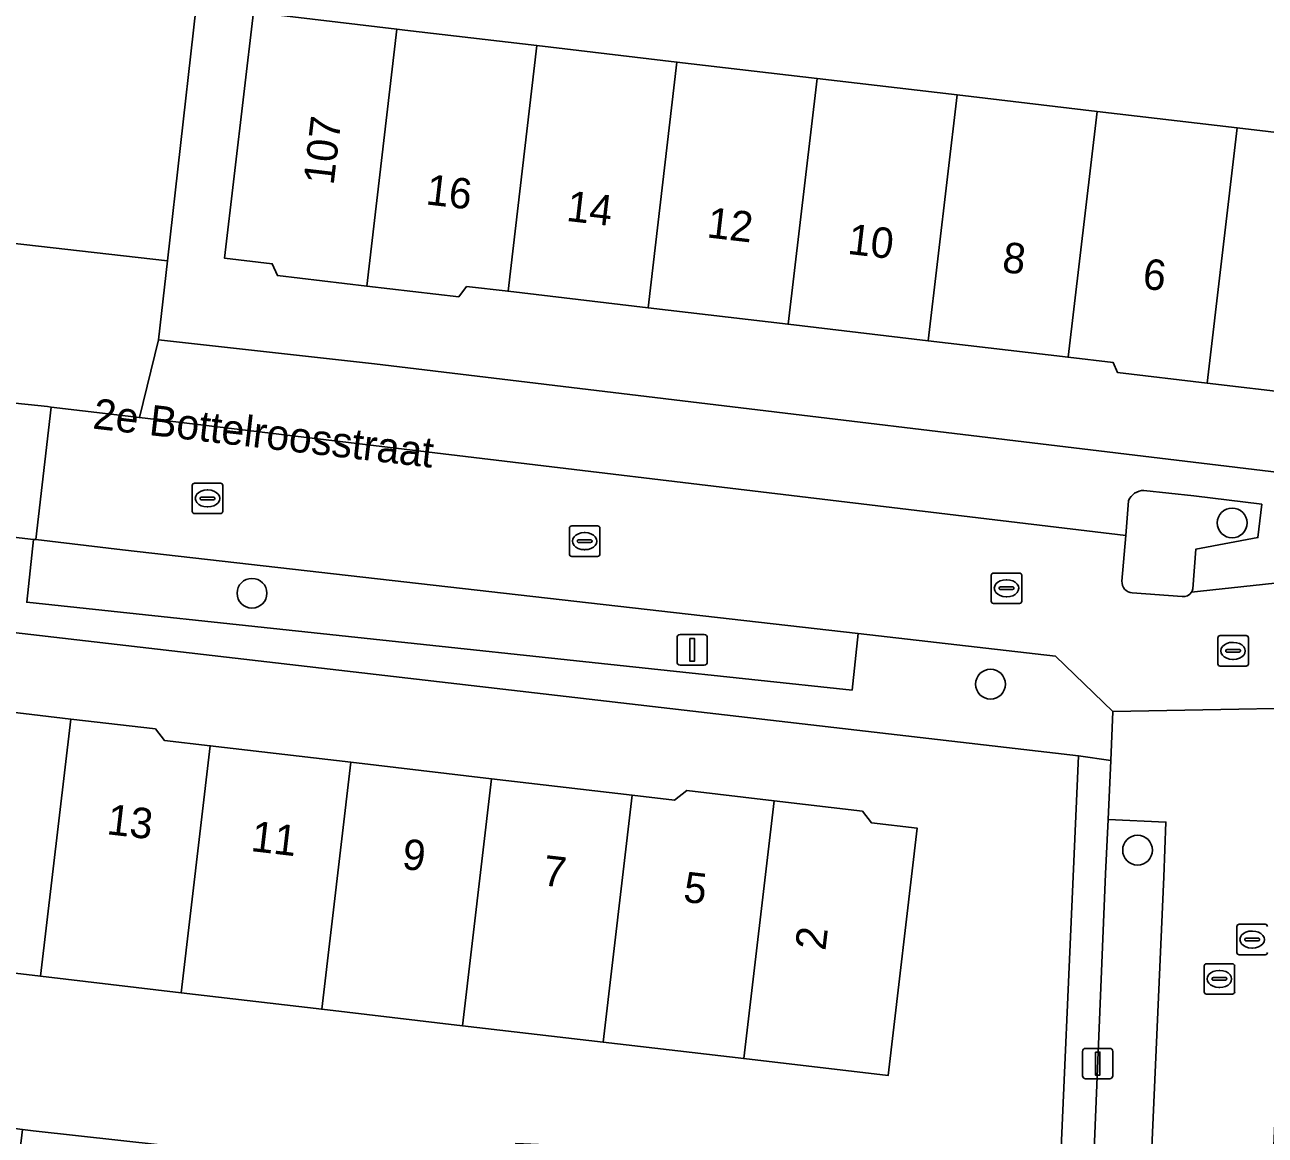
# Model space of a CAD drawing. Extents: x 162250 to 162661, y 380743 to 381606.
# Drawn here: x 162306.99 to 162347.69, y 381101.54 to 381138 of the extents above; entities that cross this region are included whole.
import ezdxf

# ---------------------------------------------------------------- set-up
doc = ezdxf.new("R2010")
doc.units = 0
for name, color, linetype in [('IMGEO_Boom', 7, 'Continuous'), ('IMGEO_Erf', 7, 'Continuous'), ('IMGEO_Groenvoorziening', 7, 'Continuous'), ('IMGEO_Kolk', 7, 'Continuous'), ('IMGEO_Lichtmast', 7, 'Continuous'), ('IMGEO_Openbare_ruimte_label', 7, 'Continuous'), ('IMGEO_Pand', 7, 'Continuous'), ('IMGEO_Pand_nummerreeks', 7, 'Continuous'), ('IMGEO_Parkeervlak_open', 7, 'Continuous'), ('IMGEO_Rijbaan_lokaal_gesloten', 7, 'Continuous'), ('IMGEO_Rijbaan_lokaal_open', 7, 'Continuous'), ('IMGEO_Rioolput', 7, 'Continuous'), ('IMGEO_Voetpad_open', 7, 'Continuous'), ('IMGEO_Woonerf_open', 7, 'Continuous')]:
    doc.layers.add(name, color=color, linetype=linetype)

msp = doc.modelspace()

# ---------------------------------------------------------------- linework, layer by layer
at = {"layer": 'IMGEO_Boom'}
for centre in [(162346.603, 381121.642), (162314.442, 381119.334), (162338.675, 381116.35), (162343.5, 381110.9)]:
    msp.add_circle(centre, 0.489, dxfattribs=at)
at = {"layer": 'IMGEO_Erf'}
for points in [[(162313.381, 381145.4), (162311.664, 381130.249), (162311.37, 381127.65), (162318.458, 381126.867), (162352.33, 381122.793), (162369.33, 381123.227), (162367.515, 381181.772)], [(162348.77, 381125.881), (162345.78, 381126.233), (162342.845, 381126.578), (162342.702, 381126.91), (162341.221, 381127.084), (162336.627, 381127.625), (162332.033, 381128.165), (162327.438, 381128.706), (162322.844, 381129.247), (162321.481, 381129.407), (162321.225, 381129.063), (162318.206, 381129.419), (162315.274, 381129.764), (162315.107, 381130.151), (162313.537, 381130.336), (162314.487, 381138.409), (162319.199, 381137.855), (162319.453, 381137.825), (162323.793, 381137.314), (162328.387, 381136.774), (162332.981, 381136.233), (162337.576, 381135.693), (162342.17, 381135.152), (162346.765, 381134.612), (162351.48, 381134.057)]]:
    msp.add_lwpolyline(points, dxfattribs=at)
for points in [[(162341.565, 381113.994), (162300.19, 381118.786), (162298.069, 381100.412), (162302.196, 381099.936), (162302.502, 381102.301), (162306.912, 381101.731), (162307.261, 381101.686), (162311.531, 381101.218), (162316.15, 381100.712), (162320.788, 381100.203), (162320.754, 381099.942), (162320.583, 381098.618), (162322.993, 381098.336), (162323.098, 381101.264), (162325.575, 381101.155), (162325.478, 381098.962), (162329.957, 381098.765), (162334.625, 381098.559), (162334.521, 381096.197), (162340.767, 381095.921)], [(162312.118, 381106.22), (162307.503, 381106.762), (162302.77, 381107.317), (162303.72, 381115.418), (162305.233, 381115.24), (162305.471, 381115.559), (162308.494, 381115.204), (162311.273, 381114.878), (162311.568, 381114.505), (162313.07, 381114.329), (162317.684, 381113.787), (162322.299, 381113.246), (162326.914, 381112.705), (162328.309, 381112.541), (162328.707, 381112.855), (162331.571, 381112.519), (162334.469, 381112.179), (162334.767, 381111.802), (162336.266, 381111.626), (162335.313, 381103.499), (162330.578, 381104.055), (162325.963, 381104.596), (162321.348, 381105.137), (162316.733, 381105.679)]]:
    msp.add_lwpolyline(points, close=True, dxfattribs=at)
at = {"layer": 'IMGEO_Groenvoorziening'}
for points in [[(162347.572, 381122.257), (162345.341, 381122.532), (162343.709, 381122.71)], [(162343.202, 381122.372), (162343.109, 381121.225), (162342.988, 381119.733)], [(162345.314, 381119.477), (162345.409, 381120.777), (162347.447, 381121.16), (162347.572, 381122.257)], [(162343.326, 381119.352), (162344.965, 381119.224)]]:
    msp.add_lwpolyline(points, dxfattribs=at)
for centre, radius, start, end in [((162343.704, 381122.168), 0.542, 89.4614, 157.9187), ((162343.34, 381119.705), 0.353, 175.4324, 267.7226), ((162345.004, 381119.537), 0.315, 262.9099, 327.1652), ((162345.019, 381119.532), 0.3, 326.4206, 349.4436)]:
    msp.add_arc(centre, radius, start, end, dxfattribs=at)
at = {"layer": 'IMGEO_Kolk'}
for p, q in [((162312.482, 381122.022), (162312.482, 381122.874)), ((162312.557, 381122.948), (162313.409, 381122.948)), ((162313.483, 381122.874), (162313.483, 381122.022)), ((162312.741, 381122.442), (162312.741, 381122.454)), ((162313.179, 381122.405), (162312.781, 381122.405)), ((162312.784, 381122.491), (162313.182, 381122.491)), ((162312.97, 381122.728), (162312.995, 381122.728)), ((162313.225, 381122.454), (162313.225, 381122.442)), ((162312.993, 381122.168), (162312.968, 381122.168)), ((162313.409, 381121.948), (162312.557, 381121.948)), ((162324.857, 381120.619), (162324.857, 381121.471)), ((162324.932, 381121.545), (162325.784, 381121.545)), ((162325.345, 381121.325), (162325.37, 381121.325)), ((162325.858, 381121.471), (162325.858, 381120.619)), ((162325.116, 381121.039), (162325.116, 381121.051)), ((162325.554, 381121.002), (162325.156, 381121.002)), ((162325.159, 381121.088), (162325.557, 381121.088)), ((162325.368, 381120.765), (162325.343, 381120.765)), ((162325.6, 381121.051), (162325.6, 381121.039)), ((162325.784, 381120.545), (162324.932, 381120.545)), ((162338.773, 381119.998), (162339.625, 381119.998)), ((162338.698, 381119.072), (162338.698, 381119.924)), ((162339, 381119.541), (162339.398, 381119.541)), ((162339.186, 381119.778), (162339.211, 381119.778)), ((162339.699, 381119.924), (162339.699, 381119.072)), ((162338.957, 381119.492), (162338.957, 381119.504)), ((162339.395, 381119.455), (162338.997, 381119.455)), ((162339.209, 381119.218), (162339.184, 381119.218)), ((162339.441, 381119.504), (162339.441, 381119.492)), ((162339.625, 381118.998), (162338.773, 381118.998)), ((162345.684, 381106.246), (162345.684, 381107.098)), ((162345.759, 381107.172), (162346.611, 381107.172)), ((162346.172, 381106.952), (162346.197, 381106.952)), ((162346.685, 381107.098), (162346.685, 381106.246)), ((162345.943, 381106.666), (162345.943, 381106.678)), ((162346.381, 381106.629), (162345.983, 381106.629)), ((162345.986, 381106.715), (162346.384, 381106.715)), ((162346.427, 381106.678), (162346.427, 381106.666)), ((162346.611, 381106.172), (162345.759, 381106.172)), ((162346.195, 381106.392), (162346.17, 381106.392))]:
    msp.add_line(p, q, dxfattribs=at)
for points in [[(162312.482, 381122.022), (162312.482, 381122.874)], [(162312.557, 381122.948), (162313.409, 381122.948)], [(162313.483, 381122.874), (162313.483, 381122.022)], [(162313.409, 381121.948), (162312.557, 381121.948)], [(162324.857, 381120.619), (162324.857, 381121.471)], [(162324.932, 381121.545), (162325.784, 381121.545)], [(162325.858, 381121.471), (162325.858, 381120.619)], [(162325.784, 381120.545), (162324.932, 381120.545)], [(162338.773, 381119.998), (162339.625, 381119.998)], [(162338.698, 381119.072), (162338.698, 381119.924)], [(162339.699, 381119.924), (162339.699, 381119.072)], [(162339.625, 381118.998), (162338.773, 381118.998)], [(162345.684, 381106.246), (162345.684, 381107.098)], [(162345.759, 381107.172), (162346.611, 381107.172)], [(162346.685, 381107.098), (162346.685, 381106.246)], [(162346.611, 381106.172), (162345.759, 381106.172)]]:
    msp.add_lwpolyline(points, dxfattribs=at)
for centre, radius, start, end in [((162312.559, 381122.872), 0.0765, 91.552, 178.448), ((162312.559, 381122.872), 0.0765, 91.552, 178.448), ((162313.407, 381122.872), 0.0765, 1.552, 88.448), ((162313.407, 381122.872), 0.0765, 1.552, 88.448), ((162312.781, 381122.451), 0.0403, 85.8775, 175.7526), ((162312.778, 381122.441), 0.0366, 178.938, 274.7102), ((162313.182, 381122.448), 0.043, 264.8664, 352.4533), ((162313.186, 381122.453), 0.0386, 1.7309, 96.639), ((162312.559, 381122.024), 0.0765, 181.552, 268.448), ((162312.559, 381122.024), 0.0765, 181.552, 268.448), ((162313.407, 381122.024), 0.0765, 271.552, 358.448), ((162313.407, 381122.024), 0.0765, 271.552, 358.448), ((162324.934, 381121.469), 0.0765, 91.552, 178.448), ((162324.934, 381121.469), 0.0765, 91.552, 178.448), ((162325.782, 381121.469), 0.0765, 1.552, 88.448), ((162325.782, 381121.469), 0.0765, 1.552, 88.448), ((162325.156, 381121.048), 0.0403, 85.8775, 175.7526), ((162325.153, 381121.038), 0.0366, 178.938, 274.7102), ((162325.557, 381121.045), 0.043, 264.8664, 352.4533), ((162325.561, 381121.05), 0.0386, 1.7309, 96.639), ((162324.934, 381120.621), 0.0765, 181.552, 268.448), ((162324.934, 381120.621), 0.0765, 181.552, 268.448), ((162325.782, 381120.621), 0.0765, 271.552, 358.448), ((162325.782, 381120.621), 0.0765, 271.552, 358.448), ((162338.775, 381119.922), 0.0765, 91.552, 178.448), ((162338.775, 381119.922), 0.0765, 91.552, 178.448), ((162339.623, 381119.922), 0.0765, 1.552, 88.448), ((162339.623, 381119.922), 0.0765, 1.552, 88.448), ((162338.997, 381119.501), 0.0403, 85.8775, 175.7526), ((162339.402, 381119.503), 0.0386, 1.7309, 96.639), ((162338.994, 381119.491), 0.0366, 178.938, 274.7102), ((162339.398, 381119.498), 0.043, 264.8664, 352.4533), ((162338.775, 381119.074), 0.0765, 181.552, 268.448), ((162338.775, 381119.074), 0.0765, 181.552, 268.448), ((162339.623, 381119.074), 0.0765, 271.552, 358.448), ((162339.623, 381119.074), 0.0765, 271.552, 358.448), ((162345.761, 381107.096), 0.0765, 91.552, 178.448), ((162345.761, 381107.096), 0.0765, 91.552, 178.448), ((162346.609, 381107.096), 0.0765, 1.552, 88.448), ((162346.609, 381107.096), 0.0765, 1.552, 88.448), ((162345.983, 381106.675), 0.0403, 85.8775, 175.7526), ((162345.98, 381106.665), 0.0366, 178.938, 274.7102), ((162346.384, 381106.672), 0.043, 264.8664, 352.4533), ((162346.388, 381106.677), 0.0386, 1.7309, 96.639), ((162345.761, 381106.248), 0.0765, 181.552, 268.448), ((162345.761, 381106.248), 0.0765, 181.552, 268.448), ((162346.609, 381106.248), 0.0765, 271.552, 358.448), ((162346.609, 381106.248), 0.0765, 271.552, 358.448)]:
    msp.add_arc(centre, radius, start, end, dxfattribs=at)
for centre, major_axis, ratio, start_param, end_param in [((162312.969, 381122.448), (-0.387, 0.002), 0.722429, 4.712389, 7.853982), ((162312.994, 381122.448), (-0.39, 0.002), 0.717154, 1.570796, 4.712389), ((162325.344, 381121.045), (-0.387, 0.002), 0.722429, 4.712389, 7.853982), ((162325.369, 381121.045), (-0.39, 0.002), 0.717154, 1.570796, 4.712389), ((162339.185, 381119.498), (-0.387, 0.002), 0.722429, 4.712389, 7.853982), ((162339.21, 381119.498), (-0.39, 0.002), 0.717154, 1.570796, 4.712389), ((162346.171, 381106.672), (-0.387, 0.002), 0.722429, 4.712389, 7.853982), ((162346.196, 381106.672), (-0.39, 0.002), 0.717154, 1.570796, 4.712389)]:
    msp.add_ellipse(centre, major_axis=major_axis, ratio=ratio, start_param=start_param, end_param=end_param, dxfattribs=at)
at = {"layer": 'IMGEO_Lichtmast'}
for p, q in [((162328.49, 381117.978), (162329.28, 381117.978)), ((162329.28, 381117.978), (162328.49, 381117.978)), ((162328.39, 381117.078), (162328.39, 381117.878)), ((162328.39, 381117.878), (162328.39, 381117.078)), ((162329.38, 381117.878), (162329.38, 381117.078)), ((162329.38, 381117.078), (162329.38, 381117.878)), ((162329.28, 381116.978), (162328.49, 381116.978)), ((162328.49, 381116.978), (162329.28, 381116.978)), ((162341.696, 381103.493), (162341.696, 381104.293)), ((162341.696, 381104.293), (162341.696, 381103.493)), ((162341.796, 381104.393), (162342.586, 381104.393)), ((162342.586, 381104.393), (162341.796, 381104.393)), ((162342.686, 381104.293), (162342.686, 381103.493)), ((162342.686, 381103.493), (162342.686, 381104.293)), ((162342.586, 381103.393), (162341.796, 381103.393)), ((162341.796, 381103.393), (162342.586, 381103.393))]:
    msp.add_line(p, q, dxfattribs=at)
for points in [[(162328.81, 381117.853), (162328.96, 381117.853), (162328.96, 381117.103), (162328.81, 381117.103), (162328.81, 381117.853)], [(162342.116, 381104.268), (162342.266, 381104.268), (162342.266, 381103.518), (162342.116, 381103.518), (162342.116, 381104.268)]]:
    msp.add_lwpolyline(points, dxfattribs=at)
for centre, start, end in [((162328.49, 381117.878), 90, 180), ((162328.49, 381117.878), 90, 180), ((162329.28, 381117.878), 0, 90), ((162329.28, 381117.878), 360, 90), ((162328.49, 381117.078), 180, 270), ((162328.49, 381117.078), 180, 270), ((162329.28, 381117.078), 270, 0), ((162329.28, 381117.078), 270, 0), ((162341.796, 381104.293), 90, 180), ((162341.796, 381104.293), 90, 180), ((162342.586, 381104.293), 0, 90), ((162342.586, 381104.293), 360, 90), ((162341.796, 381103.493), 180, 270), ((162341.796, 381103.493), 180, 270), ((162342.586, 381103.493), 270, 0), ((162342.586, 381103.493), 270, 0)]:
    msp.add_arc(centre, 0.1, start, end, dxfattribs=at)
at = {"layer": 'IMGEO_Pand'}
for points in [[(162319.199, 381137.855), (162314.487, 381138.409), (162313.537, 381130.336), (162315.107, 381130.151), (162315.274, 381129.764), (162318.206, 381129.419)], [(162319.199, 381137.855), (162318.206, 381129.419), (162321.225, 381129.063), (162321.481, 381129.407), (162322.844, 381129.247), (162323.793, 381137.314), (162319.453, 381137.825)], [(162327.438, 381128.706), (162328.387, 381136.774), (162323.793, 381137.314), (162322.844, 381129.247)], [(162332.981, 381136.233), (162328.387, 381136.774), (162327.438, 381128.706), (162332.033, 381128.165)], [(162332.981, 381136.233), (162332.033, 381128.165), (162336.627, 381127.625), (162337.576, 381135.693)], [(162342.17, 381135.152), (162337.576, 381135.693), (162336.627, 381127.625), (162341.221, 381127.084)], [(162346.765, 381134.612), (162342.17, 381135.152), (162341.221, 381127.084), (162342.702, 381126.91), (162342.845, 381126.578), (162345.78, 381126.233)], [(162346.765, 381134.612), (162345.78, 381126.233), (162348.77, 381125.881), (162348.991, 381126.176), (162350.531, 381125.995), (162351.116, 381130.961), (162351.48, 381134.057)], [(162307.503, 381106.762), (162308.494, 381115.204), (162305.471, 381115.559), (162305.233, 381115.24), (162303.72, 381115.418), (162302.77, 381107.317)], [(162307.503, 381106.762), (162312.118, 381106.22), (162313.07, 381114.329), (162311.568, 381114.505), (162311.273, 381114.878), (162308.494, 381115.204)], [(162316.733, 381105.679), (162317.684, 381113.787), (162313.07, 381114.329), (162312.118, 381106.22)], [(162322.299, 381113.246), (162317.684, 381113.787), (162316.733, 381105.679), (162321.348, 381105.137)], [(162322.299, 381113.246), (162321.348, 381105.137), (162325.963, 381104.596), (162326.914, 381112.705)], [(162325.963, 381104.596), (162330.578, 381104.055), (162331.571, 381112.519), (162328.707, 381112.855), (162328.309, 381112.541), (162326.914, 381112.705)], [(162331.571, 381112.519), (162330.578, 381104.055), (162335.313, 381103.499), (162336.266, 381111.626), (162334.767, 381111.802), (162334.469, 381112.179)], [(162311.531, 381101.218), (162307.261, 381101.686), (162306.912, 381101.731), (162306.641, 381099.418), (162311.26, 381098.913), (162311.46, 381100.618), (162311.508, 381101.021)]]:
    msp.add_lwpolyline(points, close=True, dxfattribs=at)
at = {"layer": 'IMGEO_Parkeervlak_open'}
for points in [[(162318.458, 381126.867), (162311.37, 381127.65), (162310.747, 381125.102), (162343.109, 381121.225), (162343.202, 381122.372)], [(162345.269, 381119.366), (162345.564, 381119.398), (162351.462, 381120.034), (162369.492, 381120.515), (162369.33, 381123.227), (162352.33, 381122.793), (162318.458, 381126.867)], [(162343.709, 381122.71), (162345.341, 381122.532), (162347.572, 381122.257), (162347.447, 381121.16), (162345.409, 381120.777), (162345.314, 381119.477)]]:
    msp.add_lwpolyline(points, dxfattribs=at)
for points in [[(162310.188, 381120.764), (162307.344, 381121.095), (162307.271, 381121.104), (162307.051, 381119.037), (162327.552, 381116.854), (162334.133, 381116.153), (162334.331, 381118.009)], [(162344.356, 381110.027), (162344.432, 381111.824), (162342.532, 381111.902), (162342.447, 381110.128), (162341.485, 381086.666), (162343.329, 381086.625), (162343.397, 381088.199), (162343.656, 381094.218)]]:
    msp.add_lwpolyline(points, close=True, dxfattribs=at)
for centre, radius, start, end in [((162343.704, 381122.168), 0.542, 89.4614, 157.9187), ((162345.019, 381119.532), 0.3, 326.4206, 349.4436)]:
    msp.add_arc(centre, radius, start, end, dxfattribs=at)
at = {"layer": 'IMGEO_Rijbaan_lokaal_gesloten'}
msp.add_lwpolyline([(162304.043, 381121.471), (162304.742, 381121.392), (162307.271, 381121.104), (162307.344, 381121.095), (162307.851, 381125.447), (162307.735, 381125.461), (162305.277, 381125.719)], dxfattribs=at)
at = {"layer": 'IMGEO_Rijbaan_lokaal_open'}
msp.add_lwpolyline([(162352.124, 381115.622), (162342.693, 381115.454), (162342.62, 381113.844), (162342.532, 381111.902), (162344.432, 381111.824), (162344.356, 381110.027), (162343.656, 381094.218), (162347.658, 381094.025), (162347.782, 381096.729), (162347.851, 381098.505), (162348.369, 381110.012), (162348.429, 381111.017)], dxfattribs=at)
at = {"layer": 'IMGEO_Rioolput'}
for p, q in [((162346.208, 381117.942), (162347.06, 381117.942)), ((162346.133, 381117.016), (162346.133, 381117.868)), ((162346.621, 381117.722), (162346.646, 381117.722)), ((162347.134, 381117.868), (162347.134, 381117.016)), ((162346.392, 381117.436), (162346.392, 381117.448)), ((162346.83, 381117.399), (162346.432, 381117.399)), ((162346.435, 381117.485), (162346.833, 381117.485)), ((162346.644, 381117.162), (162346.619, 381117.162)), ((162346.876, 381117.448), (162346.876, 381117.436)), ((162347.06, 381116.942), (162346.208, 381116.942)), ((162346.76, 381107.539), (162346.76, 381108.391)), ((162346.835, 381108.465), (162347.687, 381108.465)), ((162347.248, 381108.245), (162347.273, 381108.245)), ((162347.019, 381107.959), (162347.019, 381107.971)), ((162347.457, 381107.922), (162347.059, 381107.922)), ((162347.062, 381108.008), (162347.46, 381108.008)), ((162347.503, 381107.971), (162347.503, 381107.959)), ((162347.687, 381107.465), (162346.835, 381107.465)), ((162347.271, 381107.685), (162347.246, 381107.685))]:
    msp.add_line(p, q, dxfattribs=at)
for points in [[(162346.208, 381117.942), (162347.06, 381117.942)], [(162346.133, 381117.016), (162346.133, 381117.868)], [(162347.134, 381117.868), (162347.134, 381117.016)], [(162347.06, 381116.942), (162346.208, 381116.942)], [(162346.76, 381107.539), (162346.76, 381108.391)], [(162346.835, 381108.465), (162347.687, 381108.465)], [(162347.687, 381107.465), (162346.835, 381107.465)]]:
    msp.add_lwpolyline(points, dxfattribs=at)
for centre, radius, start, end in [((162346.21, 381117.866), 0.0765, 91.552, 178.448), ((162346.21, 381117.866), 0.0765, 91.552, 178.448), ((162347.058, 381117.866), 0.0765, 1.552, 88.448), ((162347.058, 381117.866), 0.0765, 1.552, 88.448), ((162346.432, 381117.445), 0.0403, 85.8775, 175.7526), ((162346.429, 381117.435), 0.0366, 178.938, 274.7102), ((162346.833, 381117.442), 0.043, 264.8664, 352.4533), ((162346.837, 381117.447), 0.0386, 1.7309, 96.639), ((162346.21, 381117.018), 0.0765, 181.552, 268.448), ((162346.21, 381117.018), 0.0765, 181.552, 268.448), ((162347.058, 381117.018), 0.0765, 271.552, 358.448), ((162347.058, 381117.018), 0.0765, 271.552, 358.448), ((162346.837, 381108.389), 0.0765, 91.552, 178.448), ((162346.837, 381108.389), 0.0765, 91.552, 178.448), ((162347.685, 381108.389), 0.0765, 1.552, 88.448), ((162347.685, 381108.389), 0.0765, 1.552, 88.448), ((162347.059, 381107.968), 0.0403, 85.8775, 175.7526), ((162347.056, 381107.958), 0.0366, 178.938, 274.7102), ((162347.46, 381107.965), 0.043, 264.8664, 352.4533), ((162347.464, 381107.97), 0.0386, 1.7309, 96.639), ((162346.837, 381107.541), 0.0765, 181.552, 268.448), ((162346.837, 381107.541), 0.0765, 181.552, 268.448), ((162347.685, 381107.541), 0.0765, 271.552, 358.448), ((162347.685, 381107.541), 0.0765, 271.552, 358.448)]:
    msp.add_arc(centre, radius, start, end, dxfattribs=at)
for centre, major_axis, ratio, start_param, end_param in [((162346.62, 381117.442), (-0.387, 0.002), 0.722429, 4.712389, 7.853982), ((162346.645, 381117.442), (-0.39, 0.002), 0.717154, 1.570796, 4.712389), ((162347.247, 381107.965), (-0.387, 0.002), 0.722429, 4.712389, 7.853982), ((162347.272, 381107.965), (-0.39, 0.002), 0.717154, 1.570796, 4.712389)]:
    msp.add_ellipse(centre, major_axis=major_axis, ratio=ratio, start_param=start_param, end_param=end_param, dxfattribs=at)
at = {"layer": 'IMGEO_Voetpad_open'}
for points in [[(162299.621, 381128.436), (162299.859, 381131.609), (162301.599, 381146.688), (162302.216, 381150.855), (162302.639, 381154.511), (162302.824, 381157.247), (162304.277, 381169.834), (162309.465, 381169.228), (162308.019, 381156.658), (162307.803, 381154.836), (162307.027, 381147.937), (162306.8, 381146.143), (162305.021, 381131.001), (162311.664, 381130.249), (162313.381, 381145.4), (162313.546, 381146.86), (162317.741, 381183.897)], [(162311.664, 381130.249), (162305.021, 381131.001), (162299.859, 381131.609), (162299.621, 381128.436)], [(162305.277, 381125.719), (162307.735, 381125.461), (162307.851, 381125.447), (162310.747, 381125.102), (162311.37, 381127.65), (162311.664, 381130.249)], [(162340.803, 381117.27), (162334.331, 381118.009), (162334.133, 381116.153), (162327.552, 381116.854), (162307.051, 381119.037), (162307.271, 381121.104), (162304.742, 381121.392), (162304.043, 381121.471)], [(162300.393, 381121.029), (162300.19, 381118.786), (162341.565, 381113.994), (162342.62, 381113.844), (162342.693, 381115.454), (162340.803, 381117.27)], [(162341.485, 381086.666), (162342.447, 381110.128), (162342.532, 381111.902), (162342.62, 381113.844), (162341.565, 381113.994), (162340.767, 381095.921)]]:
    msp.add_lwpolyline(points, dxfattribs=at)
at = {"layer": 'IMGEO_Woonerf_open'}
for points in [[(162342.988, 381119.733), (162343.109, 381121.225), (162310.747, 381125.102), (162307.851, 381125.447), (162307.344, 381121.095), (162310.188, 381120.764), (162334.331, 381118.009), (162340.803, 381117.27), (162342.693, 381115.454), (162352.124, 381115.622)], [(162352.711, 381115.731), (162355.551, 381115.867), (162356.462, 381115.897), (162369.712, 381116.357), (162369.492, 381120.515), (162351.462, 381120.034), (162345.564, 381119.398), (162345.269, 381119.366)], [(162344.965, 381119.224), (162343.326, 381119.352)]]:
    msp.add_lwpolyline(points, dxfattribs=at)
for centre, radius, start, end in [((162343.34, 381119.705), 0.353, 175.4324, 267.7226), ((162345.004, 381119.537), 0.315, 262.9099, 327.1652)]:
    msp.add_arc(centre, radius, start, end, dxfattribs=at)

# ---------------------------------------------------------------- texts
at = {"layer": 'IMGEO_Openbare_ruimte_label'}
msp.add_text('2e Bottelroosstraat', height=1, rotation=353.394, dxfattribs=at).set_placement((162309.189, 381124.745))
at = {"layer": 'IMGEO_Pand_nummerreeks'}
for s, rotation, p in [('107', 83.2885, (162317.118, 381132.711)), ('16', 353.2999, (162320.118, 381132.105)), ('14', 353.2999, (162324.73, 381131.563)), ('12', 353.2999, (162329.339, 381131.021)), ('10', 353.2999, (162333.956, 381130.479)), ('8', 353.2999, (162339.027, 381129.884)), ('6', 353.2999, (162343.635, 381129.342)), ('13', 353.3088, (162309.649, 381111.427)), ('11', 353.3088, (162314.377, 381110.873)), ('9', 353.3088, (162319.336, 381110.29)), ('7', 353.3088, (162323.951, 381109.749)), ('5', 353.3088, (162328.566, 381109.208)), ('2', 83.3118, (162333.255, 381107.58))]:
    msp.add_text(s, height=1, rotation=rotation, dxfattribs=at).set_placement(p)

doc.saveas('drawing.dxf')
